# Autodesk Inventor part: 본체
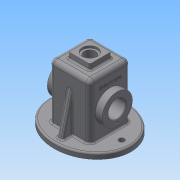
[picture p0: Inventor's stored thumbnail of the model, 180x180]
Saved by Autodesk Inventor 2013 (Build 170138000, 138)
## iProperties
Created: 2017-07
Part Number: 본체
Material: Generic
Document SubType Name: Modeling
Designer: Administrator
Density: 1 g/cm^3
Author: Administrator
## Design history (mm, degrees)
sketch "스케치2"
  geometry: L1 (37, -37)-(-37, -37); L2 (-37, -37)-(-37, 37); L3 (-37, 37)-(37, 37); L4 (37, 37)-(37, -37); L5 (37, -37)-(-37, 37); L6 (-37, -37)-(37, 37); 1 further point
  constraints: 12 end point, 2 midpoint, 2 parallel, 1 horizontal, 1 perpendicular
  dimensions: "d0" = 74 distance of L2.end L3.end; "d2" = 74 distance of L1.end L2.end
extrude "돌출1" new body sketch "스케치2" distance "d3" = 100; taper "d4" = 0 deg
feature "쉘1" dims "d5" = 5
fillet "모깎기1" dims "d6" = 3
fillet "모깎기2" dims "d7" = 8
sketch "스케치4" dims "d8" = 65, "d10" = 75
  geometry: L1 (29, 29)-(29, -29) reference; L2 (-29, 29)-(29, 29) reference; L3 (-29, -29)-(-29, 29) reference; L4 (29, -29)-(-29, -29) reference; L5 (0, 0)-(-58, 0); L6 (0, 0)-(58, 0); L7 (-29, -32)-(29, -32) reference; L8 (32, -29)-(32, 29) reference; L9 (29, 32)-(-29, 32) reference; L10 (-32, 29)-(-32, -29) reference; L11 (37, 29)-(37, -29) reference; L12 (29, -37)-(-29, -37) reference; L13 (-37, -29)-(-37, 29) reference; L14 (-29, 37)-(29, 37) reference; C1 r 5 at (-58, 0); C2 r 5 at (58, 0); A1 r 3 centre (29, -29) between (29, -32) and (32, -29) reference; A2 r 3 centre (29, 29) between (32, 29) and (29, 32) reference; A3 r 3 centre (-29, 29) between (-29, 32) and (-32, 29) reference; A4 r 3 centre (-29, -29) between (-32, -29) and (-29, -32) reference; A5 r 8 centre (29, 29) between (37, 29) and (29, 37) reference; A6 r 8 centre (29, -29) between (29, -37) and (37, -29) reference; A7 r 8 centre (-29, -29) between (-37, -29) and (-29, -37) reference; A8 r 8 centre (-29, 29) between (-29, 37) and (-37, 29) reference; 2 further points; 1 other entity
  constraints: 4 coincident, 4 end point, 2 centre point, 2 horizontal, 1 collinear, 2 other
  dimensions: "d11" = 58 distance of L5.start L5.end; "d12" = 10 diameter of C1; "d13" = 58 distance of L5.start L6.end; "d14" = 10 diameter of C2
  node "투영된 루프1"
  node "투영된 루프3"
sketch "스케치5"
  geometry: L1 (92, -36)-(92, 94) reference; L2 (92, 29)-(47, 29); C1 r 27.5 at (47, 29); 1 further point
  constraints: 2 end point, 1 centre point, 1 coincident, 1 midpoint, 1 perpendicular
  dimensions: "d18" = 45 distance of L2.start L2.end; "d20" = 55 diameter of C1
extrude "돌출3" join sketch "스케치5" distance "d21" = 13; taper "d22" = 0 deg
fillet "모깎기4" dims "d23" = 0.5
sketch "스케치6"
  geometry: L1 (-92, 94)-(-92, -36) reference; L2 (-92, 29)-(-47, 29); C1 r 27.5 at (-47, 29); 1 further point
  constraints: 2 end point, 1 centre point, 1 coincident, 1 midpoint, 1 perpendicular
  dimensions: "d24" = 45 distance of L2.start L2.end; "d26" = 55 diameter of C1
extrude "돌출4" join sketch "스케치6" distance "d27" = 13; taper "d28" = 0 deg
fillet "모깎기5" dims "d29" = 0.5
sketch "스케치7"
  geometry: C1 r 27.5 at (0, 0) reference; C2 r 16 at (0, 0); 1 further point
  constraints: 1 centre point, 1 coincident
  dimensions: "d30" = 32 diameter of C2
extrude "돌출5" cut sketch "스케치7" stored distance "d32" = 13; taper "d33" = 0 deg
chamfer "모따기1" distance "d34" = 1; stored, may be unused: second distance "d35" = 2, angle "d36" = 45 deg
sketch "스케치8"
  geometry: L1 (29, -10)-(-29, -10) reference; L2 (-50, 62)-(-50, 28) reference; L3 (50, 28)-(50, 62) reference; L4 (-50, 45)-(50, 45); L5 (-49, 61)-(-32, 61) reference; L6 (50, 17.5)-(50, 72.5) reference; L7 (37.5, 72.5)-(37.5, 17.5) reference; L8 (32, 61)-(49, 61) reference; L9 (-32, 92)-(-32, 0) reference; L10 (32, 0)-(32, 92) reference; L11 (-32, 45)-(-32, 61); L12 (-32, 61)-(-25, 61); L13 (-32, 72.5)-(-25, 65.5); L14 (-25, 61)-(-25, 65.5); L15 (32, 45)-(32, 61); L16 (32, 61)-(25, 61); L17 (25, 61)-(25, 65.5); L18 (25, 65.5)-(32, 72.5); L19 (-32, 61)-(-32, 72.5); L20 (32, 61)-(32, 72.5); 1 further point
  constraints: 22 end point, 6 point on line, 5 perpendicular, 4 collinear, 2 midpoint
  dimensions: "d37" = 7 distance of L5.end L12.end; "d39" = 55 diameter of L13.start L4; "d40" = 135 deg angle of L9 L13; "d41" = 7 distance of L8.start L16.end; "d42" = 4.5 distance of L16.end L17.end
  node "투영된 루프2"
revolve "회전1" stored, may be unused: angle "d43" = 90 deg
extrude "돌출6" join sketch "스케치4" distance "d44" = 10; taper "d45" = 0 deg
fillet "모깎기6" dims "d46" = 3
fillet "모깎기7" dims "d47" = 0.5
revolve "회전2" stored, may be unused: angle "d48" = 90 deg
fillet "모깎기8" dims "d49" = 0.5
sketch "스케치9"
  geometry: L1 (-17, -20)-(17, -20); L2 (20, -17)-(20, 17); L3 (17, 20)-(-17, 20); L4 (-20, 17)-(-20, -17); L5 (-20, -20)-(20, 20); L6 (20, -20)-(-20, 20); A1 r 3 centre (-17, 17) between (-17, 20) and (-20, 17); A2 r 3 centre (-17, -17) between (-20, -17) and (-17, -20); A3 r 3 centre (17, -17) between (17, -20) and (20, -17); A4 r 3 centre (17, 17) between (20, 17) and (17, 20); 1 further point
  constraints: 12 end point, 8 point on circle, 8 point on line, 8 tangent, 4 centre point, 3 equal radius, 2 midpoint, 2 parallel, 1 horizontal, 1 perpendicular
  dimensions: "d52" = 40 distance of L5.end L6.end; "d54" = 40 distance of L6.end L5.start; "d55" = 3 radius of A1
extrude "돌출7" join sketch "스케치9" distance "d56" = 10; taper "d57" = -5 deg
fillet "모깎기9" dims "d58" = 3
sketch "스케치10"
  geometry: C1 r 14 at (0, 0); 1 further point
  constraints: 1 centre point, 1 coincident
  dimensions: "d59" = 28 diameter of C1
extrude "돌출8" cut sketch "스케치10" distance "d61" = 4; taper "d62" = 0 deg
sketch "스케치11"
  geometry: C1 r 14 at (0, 0) reference; C2 r 10.5 at (0, 0)
  constraints: 1 centre point, 1 coincident
  dimensions: "d63" = 21 diameter of C2
extrude "돌출9" cut sketch "스케치11" stored distance "d65" = 4; taper "d66" = 0 deg
sketch "스케치12" dims "d67" = 45
  geometry: L1 (0, 0)-(0, 22.5); C1 r 17 at (0, 0) reference; C2 r 2 at (0, 22.5); 1 further point
  constraints: 2 coincident, 2 end point, 1 centre point, 1 vertical, 1 vertical alignment, 2 other
  dimensions: "d69" = 4 diameter of C2
hole "구멍1" sketch "스케치12" at (0, 22.5) diameter "d70" = 3.242; stored, may be unused: countersink angle "d74" = 90 deg, drill point angle "d76" = 118 deg; dims "d71" = 8, "d72" = 4, "d73" = 2, "d75" = 10
sketch "스케치13" dims "d80" = 45
  geometry: L1 (0, 0)-(0, 22.5); C1 r 17 at (0, 0) reference; C2 r 2 at (0, 22.5); 1 further point
  constraints: 2 coincident, 2 end point, 1 centre point, 1 vertical, 1 vertical alignment, 2 other
  dimensions: "d82" = 4 diameter of C2
hole "구멍2" sketch "스케치13" at (0, 22.5) diameter "d83" = 3.242; stored, may be unused: countersink angle "d87" = 90 deg, drill point angle "d89" = 118 deg; dims "d84" = 8, "d85" = 4, "d86" = 2, "d88" = 10
sketch "스케치14"
  geometry: L1 (-37, 0)-(-37, 92) reference; L2 (37, 92)-(37, 0) reference; L3 (29, -10)-(-29, -10) reference; L4 (-65, -10)-(65, -10) reference; L5 (-65, -10)-(-65, 0); L6 (-55, 0)-(-55, -10); L7 (-65, 0)-(-55, 0); L8 (-55, 0)-(-37, 72.194); L9 (65, -10)-(65, 0); L10 (55, -10)-(55, 0); L11 (65, 0)-(55, 0); L12 (55, 0)-(37, 72.194); L13 (-37, 72.194)-(-37, 0); L14 (37, 72.194)-(37, 0); L15 (55, 0)-(37, 0); L16 (-37, 0)-(-55, 0); 1 further point
  constraints: 24 end point, 5 point on line, 4 perpendicular, 2 collinear, 1 vertical
  dimensions: "d95" = 10 distance of L4.start L5.end; "d96" = 10 distance between parallel lines of L5 L6; "d98" = 10 distance of L6.start L6.end; "d99" = 14 deg angle of L5 L8; "d100" = 10 distance of L4.end L9.end; "d102" = 10 distance of L10.start L10.end; "d103" = 10 distance between parallel lines of L9 L10; "d104" = 14 deg angle of L9 L12
extrude "돌출10" join sketch "스케치14" stored distance "d105" = 10; taper "d106" = 0 deg
fillet "모깎기10" dims "d107" = 3
fillet "모깎기11" dims "d108" = 3
sketch "스케치15"
  geometry: L1 (7.189, 8.261)-(7.189, 49.739); L2 (7.189, 49.739)-(16.811, 49.739); L3 (16.811, 49.739)-(16.811, 8.261); L4 (16.811, 8.261)-(7.189, 8.261); L5 (12, 8.261)-(12, 49.739); L6 (7.189, 29)-(16.811, 29); L7 (89, 66)-(0, 66) reference; L8 (-8, 58)-(-8, 0) reference; L9 (-18, 46)-(-18, 12) reference; 1 further point
  constraints: 4 end point, 4 midpoint, 2 other
  dimensions: "d109" = 37 distance between parallel lines of L7 L6; "d111" = 30 distance between parallel lines of L9 L5
extrude "돌출11" join sketch "스케치15" distance "d112" = 0.5; taper "d113" = 0 deg
node "솔리드1"
pattern_circular "원형 패턴1" dims angle "d78" = 360 deg
pattern_circular "원형 패턴2" dims "d91" = 360 deg
